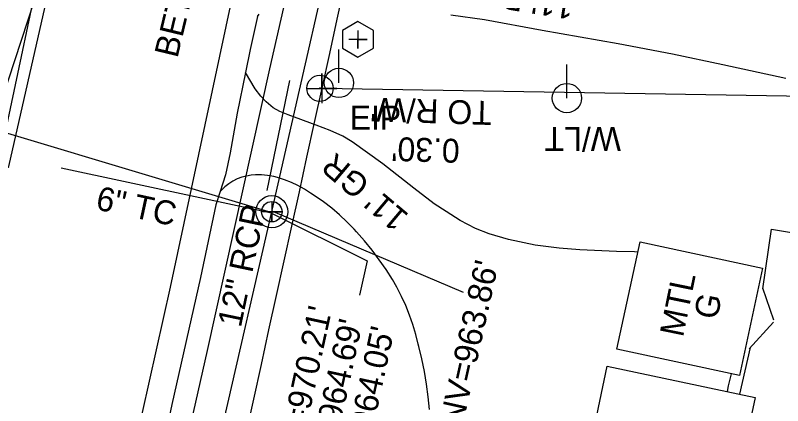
# Model space of a CAD drawing. Extents: x 1614611 to 1617571, y 898867 to 905462.
# Drawn here: x 1616262.4 to 1616390.9, y 900016.9 to 900082.2 of the extents above; entities that cross this region are included whole.
import ezdxf

# ---------------------------------------------------------------- set-up
doc = ezdxf.new("R2010")
doc.units = 0
for name, color, linetype in [('Exist Building', 7, 'Continuous'), ('Exist Building Metal Canopy', 7, 'Continuous'), ('Exist Building Text', 7, 'Continuous'), ('Exist Drainage Structure Drop Inlet CELL', 7, 'Continuous'), ('Exist Other Culture Fence Line', 7, 'Continuous'), ('Exist Other Culture Gate', 7, 'Continuous'), ('Exist Plan Preparation Watershed Yellow', 7, 'Continuous'), ('Exist Roads EOP Other Text', 7, 'Continuous'), ('Exist Roads EOP Text', 7, 'Continuous'), ('Exist Roads Soil', 7, 'Continuous'), ('Exist Utilities Gas UG Line SUE LOS B', 7, 'Continuous'), ('Exist Utilities Power Pole CELL', 7, 'Continuous'), ('Exist Utilities Power Pole Text', 7, 'Continuous'), ('Exist Utilities Sanitary Sewer AG Line Leader', 7, 'Continuous'), ('Exist Utilities Sanitary Sewer Forced Main SUE LOS C', 7, 'Continuous'), ('Exist Utilities Sanitary Sewer Forced Main SUE LOS C Invert Elevation', 7, 'Continuous'), ('Exist Utilities Sanitary Sewer Manhole Text', 7, 'Continuous'), ('Exist Utilities Sanitary Sewer Manhole Top Elevation', 7, 'Continuous'), ('Exist Utilities Sanitary Sewer UG Line', 7, 'Continuous'), ('Exist Utilities Sanitary Sewer UG Line Invert Elevation', 7, 'Continuous'), ('Exist Utilities Telephone UG Cable SUE LOS B', 7, 'Continuous'), ('Exist Utilities Telephone UG Cable SUE LOS C', 7, 'Continuous'), ('Exist Utilities Telephone UG FO SUE LOS B', 7, 'Continuous'), ('Exist Utilities Water UG Line SUE LOS B', 7, 'Continuous'), ('Old_Level_21', 7, 'Continuous'), ('Prop Drainage Structure Catch Basin Open Throat 4 Label', 7, 'Continuous'), ('Prop Drainage Structure Pipe Alternate 30in Label', 7, 'Continuous'), ('Prop Drainage Structure Pipe Stub Out CELL', 7, 'Continuous'), ('Prop Drainage Structure Tops and Inverts LABEL', 7, 'Continuous'), ('Prop Earthen Structure Cut Ditch Special Back of Curb Detail Label', 7, 'Continuous'), ('Prop Earthen Structure Head Ditch Label', 7, 'Continuous'), ('Prop Plan Preparation Grade to Drain Arrows CELL', 7, 'Continuous'), ('Scratch_Level_1', 7, 'Continuous'), ('Scratch_Level_9', 7, 'Continuous')]:
    doc.layers.add(name, color=color, linetype=linetype)

msp = doc.modelspace()

# ---------------------------------------------------------------- linework, layer by layer
at = {"layer": 'Exist Building'}
msp.add_lwpolyline([(1616347.86, 899972.69), (1616355.22, 900007.36), (1616358.99, 900006.56), (1616359.55, 900009.18), (1616358.57, 900009.38), (1616361.57, 900023.54), (1616386.33, 900018.28), (1616382.83, 900001.81), (1616387.04, 900000.92), (1616379.61, 899965.95)], close=True, dxfattribs=at)
at = {"layer": 'Exist Building Metal Canopy'}
msp.add_lwpolyline([(1616367.05, 900044.32), (1616387.56, 900039.9), (1616383.69, 900021.95), (1616363.18, 900026.37)], close=True, dxfattribs=at)
at = {"layer": 'Exist Other Culture Fence Line'}
msp.add_line((1616385.51, 900026.65), (1616383.69, 900018.84), dxfattribs=at)
msp.add_lwpolyline([(1616387.61, 900036.44), (1616389.07, 900046.43), (1616415.5, 900042.05), (1616447.47, 900036.61), (1616478.87, 900031.28), (1616498.62, 900027.77), (1616492.46, 899994.71), (1616485.93, 899960.13), (1616482.98, 899943.54), (1616459.55, 899946.51), (1616430.58, 899950.18), (1616398.99, 899954.22), (1616375.36, 899957.26)], dxfattribs=at)
at = {"layer": 'Exist Other Culture Gate'}
for p, q in [((1616387.55, 900036.64), (1616389.39, 900031.27)), ((1616385.32, 900026.44), (1616389.39, 900030.88))]:
    msp.add_line(p, q, dxfattribs=at)
at = {"layer": 'Exist Plan Preparation Watershed Yellow'}
for radius in [2.2, 0.0707]:
    msp.add_circle((1616313.44, 900070.02), radius, dxfattribs=at)
at = {"layer": 'Exist Roads Soil'}
for points in [[(1616366.67, 900042.58), (1616366.1, 900042.63), (1616363.12, 900042.71), (1616356.95, 900042.96), (1616353.52, 900043.24), (1616349.48, 900043.78), (1616345.03, 900044.74), (1616341.8, 900045.67), (1616339.47, 900046.54), (1616336.91, 900047.87), (1616334.6, 900049.39), (1616332.56, 900050.68), (1616329.16, 900053.3), (1616323.96, 900057.38), (1616318.85, 900061.07), (1616317.26, 900061.99), (1616315.17, 900062.97), (1616312.78, 900063.84), (1616308.14, 900065.56), (1616306.74, 900066.12), (1616305.61, 900066.76), (1616304.43, 900067.74), (1616303.52, 900068.69), (1616302.58, 900069.93), (1616300.95, 900072.66)], [(1616331.8, 900016.24), (1616331.59, 900018.38), (1616331.3, 900020.52), (1616330.94, 900022.64), (1616330.5, 900024.75), (1616329.98, 900026.83), (1616329.89, 900027.18), (1616329.48, 900028.83), (1616329, 900030.46), (1616328.44, 900032.07), (1616327.81, 900033.65), (1616327.1, 900035.2), (1616326.32, 900036.71), (1616325.58, 900038), (1616324.51, 900039.69), (1616323.37, 900041.33), (1616322.17, 900042.93), (1616320.9, 900044.48), (1616319.57, 900045.97), (1616319.16, 900046.42), (1616317.96, 900047.65), (1616316.71, 900048.82), (1616315.4, 900049.93), (1616314.05, 900050.99), (1616312.65, 900051.97), (1616311.87, 900052.48), (1616310.84, 900053.14), (1616309.76, 900053.74), (1616308.65, 900054.26), (1616307.51, 900054.71), (1616306.34, 900055.09), (1616305.69, 900055.26), (1616304.68, 900055.43), (1616303.67, 900055.51), (1616302.65, 900055.52), (1616301.94, 900055.48), (1616301.13, 900055.34), (1616300.35, 900055.13), (1616299.59, 900054.84), (1616298.86, 900054.47), (1616298.17, 900054.04), (1616297.52, 900053.54), (1616296.93, 900052.98), (1616296.73, 900052.77)], [(1616381.71, 900019.26), (1616381.88, 900020.2), (1616382.35, 900022.24)]]:
    msp.add_lwpolyline(points, dxfattribs=at)
at = {"layer": 'Exist Utilities Gas UG Line SUE LOS B'}
msp.add_lwpolyline([(1616228.95, 899933.49), (1616238.93, 899978.7), (1616250.88, 900021.2), (1616259.71, 900057.93), (1616268.22, 900097.82), (1616270.1, 900108.73), (1616270.66, 900110.37), (1616273.78, 900123.94), (1616283.72, 900168.25), (1616296.04, 900222.38), (1616305.4, 900264.37), (1616315.91, 900311.24), (1616322.64, 900340.02), (1616331.7, 900383.47)], dxfattribs=at)
at = {"layer": 'Exist Utilities Power Pole CELL'}
for p, q in [((1616316.61, 900070.92), (1616316.61, 900076.54)), ((1616354.8, 900068.38), (1616354.8, 900074)), ((1616316.61, 900070.92), (1616316.61, 900070.92)), ((1616354.8, 900068.38), (1616354.8, 900068.38))]:
    msp.add_line(p, q, dxfattribs=at)
for centre in [(1616316.61, 900070.92), (1616354.8, 900068.38)]:
    msp.add_circle(centre, 2.45, dxfattribs=at)
at = {"layer": 'Exist Utilities Sanitary Sewer AG Line Leader'}
msp.add_lwpolyline([(1616305.32, 900049.13), (1616321.32, 900041.15), (1616320.05, 900035.38)], dxfattribs=at)
at = {"layer": 'Exist Utilities Sanitary Sewer Forced Main SUE LOS C'}
msp.add_lwpolyline([(1615987.8, 900124.36), (1615996.95, 900123.07), (1616029.07, 900117.94), (1616050.03, 900113.65), (1616071.5, 900109.18), (1616143.09, 900093.88), (1616176.95, 900086.31), (1616208.03, 900078.35), (1616239.83, 900068.88), (1616305.38, 900049.26)], dxfattribs=at)
at = {"layer": 'Exist Utilities Sanitary Sewer Forced Main SUE LOS C Invert Elevation'}
msp.add_lwpolyline([(1616305.48, 900049.48), (1616337.45, 900035.9)], dxfattribs=at)
at = {"layer": 'Exist Utilities Sanitary Sewer UG Line'}
for p, q in [((1616305.32, 900049.13), (1616270.08, 900056.66)), ((1616249.82, 899808.06), (1616305.32, 900049.13))]:
    msp.add_line(p, q, dxfattribs=at)
msp.add_lwpolyline([(1616305.43, 900049.6), (1616345.82, 900226.73), (1616377.74, 900378.04)], dxfattribs=at)
at = {"layer": 'Exist Utilities Telephone UG Cable SUE LOS B'}
msp.add_lwpolyline([(1616244.2, 900051.3), (1616247.08, 900051.95), (1616254.34, 900051.12), (1616261.35, 900056.95), (1616270.62, 900097.78), (1616272.63, 900108.4), (1616271.69, 900124.33), (1616281.5, 900168.7), (1616293.72, 900221.15), (1616303.1, 900263.43), (1616314, 900311.75), (1616319.02, 900336.01), (1616313.74, 900338.14), (1616311.89, 900339.38)], dxfattribs=at)
at = {"layer": 'Exist Utilities Telephone UG Cable SUE LOS C'}
msp.add_lwpolyline([(1616244.2, 900051.3), (1616248.43, 900052.69), (1616253.12, 900054.18), (1616256.06, 900055.79), (1616257.99, 900061.57), (1616266.68, 900088.03), (1616271.15, 900108.67), (1616270.12, 900124.07), (1616271.06, 900129.11), (1616277.99, 900165.03), (1616284.33, 900194.68), (1616292.87, 900230.63), (1616300.4, 900263.94), (1616307.49, 900293.65), (1616316.18, 900332.48), (1616316.31, 900333.6), (1616315.2, 900335.07), (1616313.08, 900336.87), (1616311.89, 900339.38)], dxfattribs=at)
at = {"layer": 'Exist Utilities Telephone UG FO SUE LOS B'}
msp.add_lwpolyline([(1616264.27, 899888.11), (1616275.63, 899938.03), (1616283.17, 899975.46), (1616294.6, 900026.16), (1616305.05, 900073.25), (1616315.15, 900117.57), (1616325.55, 900164.34), (1616332.62, 900198.17), (1616344.78, 900239.81), (1616353.34, 900285.35), (1616361.31, 900327.32), (1616372.74, 900375.18)], dxfattribs=at)
at = {"layer": 'Exist Utilities Water UG Line SUE LOS B'}
msp.add_lwpolyline([(1616263.66, 899921.5), (1616269.73, 899949.09), (1616273.73, 899969.37), (1616281.36, 900005.29), (1616288.43, 900036.76), (1616298.97, 900086.16), (1616304.15, 900111.94), (1616312.34, 900147.74), (1616321.8, 900194.38), (1616329.08, 900224.67), (1616335.91, 900255.64), (1616338.25, 900266.44), (1616344.58, 900294.92), (1616354.08, 900334.27), (1616364.03, 900380.59)], dxfattribs=at)
at = {"layer": 'Old_Level_21'}
msp.add_lwpolyline([(1616305.38, 900051.07), (1616305.38, 900047.65), (1616305.38, 900049.36), (1616307.09, 900049.36), (1616303.66, 900049.36)], dxfattribs=at)
for radius in [2.69, 1.71]:
    msp.add_circle((1616305.38, 900049.36), radius, dxfattribs=at)
at = {"layer": 'Prop Drainage Structure Pipe Alternate 30in Label'}
msp.add_lwpolyline([(1616465.12, 899846.25), (1616513.43, 900066.7), (1616313.74, 900070.01)], dxfattribs=at)
at = {"layer": 'Prop Drainage Structure Pipe Stub Out CELL'}
msp.add_line((1616319.8, 900078.21), (1616319.8, 900078.21), dxfattribs=at)
msp.add_lwpolyline([(1616317.22, 900079.7), (1616317.22, 900076.72), (1616319.8, 900075.23), (1616322.38, 900076.71), (1616322.39, 900079.69), (1616319.81, 900081.19)], close=True, dxfattribs=at)
msp.add_lwpolyline([(1616319.8, 900079.72), (1616319.8, 900076.7), (1616319.8, 900078.21), (1616321.32, 900078.21), (1616318.29, 900078.21)], dxfattribs=at)
at = {"layer": 'Prop Drainage Structure Tops and Inverts LABEL'}
msp.add_line((1616313.74, 900070.01), (1616313.74, 900070.01), dxfattribs=at)
msp.add_lwpolyline([(1616311.24, 900070.01), (1616316.24, 900070.01), (1616313.74, 900070.01), (1616313.74, 900072.51), (1616313.74, 900067.51)], dxfattribs=at)
at = {"layer": 'Prop Earthen Structure Cut Ditch Special Back of Curb Detail Label'}
msp.add_line((1616304.57, 900052.92), (1616308.42, 900071.34), dxfattribs=at)
at = {"layer": 'Prop Earthen Structure Head Ditch Label'}
msp.add_arc((1713946.87, 878581.13), 99970, 167.4989737, 167.7161189, dxfattribs=at)
at = {"layer": 'Scratch_Level_1'}
for points in [[(1616303, 900082.04), (1616303.24, 900082.44)], [(1616335.37, 900082.34), (1616341.01, 900081.51), (1616350.66, 900079.77), (1616363.36, 900077.54), (1616372.51, 900075.78), (1616380.91, 900074.03), (1616391.49, 900071.73)]]:
    msp.add_lwpolyline(points, dxfattribs=at)
at = {"layer": 'Scratch_Level_9'}
msp.add_lwpolyline([(1616303, 900082.04), (1616301.73, 900076.5), (1616300.95, 900072.66), (1616299.56, 900065.87), (1616298.41, 900059.23), (1616297.61, 900055.52), (1616296.73, 900052.77), (1616296, 900050.49), (1616293.41, 900038.36), (1616288.61, 900017.08), (1616282.62, 899988.74), (1616279.86, 899976.28), (1616277.27, 899964.58), (1616271.56, 899939.58), (1616266.09, 899914.95)], dxfattribs=at)

# ---------------------------------------------------------------- texts
at = {"layer": 'Exist Building Text'}
for s, p in [('MTL', (1616374.24, 900028.24)), ('G', (1616379.95, 900031.16))]:
    msp.add_text(s, height=4, rotation=78.4162, dxfattribs=at).set_placement(p)
at = {"layer": 'Exist Drainage Structure Drop Inlet CELL'}
msp.add_text('EIP', height=4, dxfattribs=at).set_placement((1616318.41, 900063.12))
at = {"layer": 'Exist Roads EOP Other Text'}
for s, rotation, p in [("11' BST", 170.976, (1616356.21, 900085.43)), ("11' GR", 139.8334, (1616328.51, 900048.82))]:
    msp.add_text(s, height=4, rotation=rotation, dxfattribs=at).set_placement(p)
at = {"layer": 'Exist Roads EOP Text'}
msp.add_text('BETHANIA-RURAL HALL ROAD ', height=4, rotation=76.5207, dxfattribs=at).set_placement((1616289.56, 900074.95))
at = {"layer": 'Exist Utilities Power Pole Text'}
msp.add_text('W/LT', height=4, rotation=180, dxfattribs=at).set_placement((1616363.85, 900063.55))
at = {"layer": 'Exist Utilities Sanitary Sewer Forced Main SUE LOS C Invert Elevation'}
msp.add_text("INV=963.86'", height=4, rotation=77.4736, dxfattribs=at).set_placement((1616337.01, 900011.95))
at = {"layer": 'Exist Utilities Sanitary Sewer Manhole Text'}
msp.add_text('6" TC ', height=4, rotation=347.7588, dxfattribs=at).set_placement((1616275.71, 900049.79))
at = {"layer": 'Exist Utilities Sanitary Sewer Manhole Top Elevation'}
msp.add_text("TOP=970.21'", height=4, rotation=77.7588, dxfattribs=at).set_placement((1616308.81, 900002.26))
at = {"layer": 'Exist Utilities Sanitary Sewer UG Line Invert Elevation'}
for s, p in [("INV=964.69'", (1616314.38, 900002.12)), ("INV=964.05'", (1616319.71, 900000.88))]:
    msp.add_text(s, height=4, rotation=77.7588, dxfattribs=at).set_placement(p)
at = {"layer": 'Prop Drainage Structure Catch Basin Open Throat 4 Label'}
for s, p in [("TO R/W' ", (1616342.26, 900067.87)), ("0.30'", (1616336.9, 900061.53))]:
    msp.add_text(s, height=4, rotation=178.2617, dxfattribs=at).set_placement(p)
at = {"layer": 'Prop Plan Preparation Grade to Drain Arrows CELL'}
msp.add_text('12" RCP', height=4, rotation=78.1959, dxfattribs=at).set_placement((1616300.18, 900029.85))

doc.saveas('drawing.dxf')
